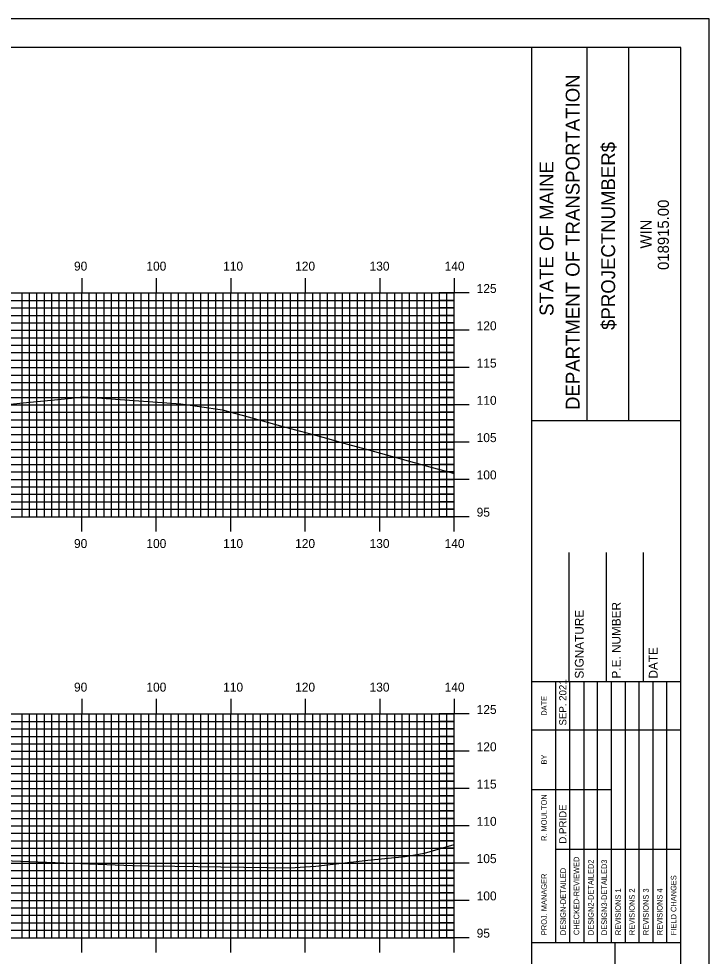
# Model space of a CAD drawing. Extents: x 1754708 to 1755051, y 442591 to 442811.
# Drawn here: x 1754955.1 to 1755047.7, y 442684.8 to 442810.5 of the extents above; entities that cross this region are included whole.
import ezdxf

# ---------------------------------------------------------------- set-up
doc = ezdxf.new("R2010")
doc.units = 0
for name, color, linetype in [('BORDER', 7, 'Continuous'), ('H_V ANNOTATION', 7, 'Continuous'), ('MAJOR', 7, 'Continuous'), ('MINOR', 7, 'Continuous'), ('PLOT BOUNDARY', 7, 'Continuous'), ('S_Roadway_Centerline', 7, 'Continuous')]:
    doc.layers.add(name, color=color, linetype=linetype)

msp = doc.modelspace()

# ---------------------------------------------------------------- linework, layer by layer
at = {"layer": 'BORDER'}
for p, q in [((1755023.92, 442596.67), (1755023.92, 442806.67)), ((1755031.37, 442756.66), (1755031.37, 442806.66)), ((1755036.96, 442756.66), (1755036.96, 442806.66)), ((1755023.92, 442756.65), (1755043.92, 442756.65)), ((1755028.92, 442721.67), (1755028.92, 442738.97)), ((1755033.92, 442721.67), (1755033.92, 442738.97)), ((1755038.92, 442721.67), (1755038.92, 442738.97)), ((1755023.92, 442721.67), (1755043.92, 442721.67)), ((1755023.92, 442686.67), (1755043.92, 442686.67)), ((1755035.1, 442616.67), (1755035.1, 442686.67))]:
    msp.add_line(p, q, dxfattribs=at)
msp.add_lwpolyline([(1754723.92, 442596.67), (1755043.92, 442596.67), (1755043.92, 442806.67), (1754723.92, 442806.67)], close=True, dxfattribs=at)
for points in [[(1755027.15, 442715.17), (1755027.15, 442721.67)], [(1755029.01, 442686.68), (1755029.01, 442721.67)], [(1755030.88, 442721.67), (1755030.88, 442686.68)], [(1755032.74, 442686.68), (1755032.74, 442721.67)], [(1755034.6, 442686.68), (1755034.6, 442721.67)], [(1755036.47, 442686.68), (1755036.47, 442721.67)], [(1755038.33, 442686.68), (1755038.33, 442721.67)], [(1755040.19, 442686.68), (1755040.19, 442721.67)], [(1755042.06, 442686.68), (1755042.06, 442721.67)], [(1755027.15, 442686.68), (1755027.15, 442720.26)], [(1755023.92, 442715.17), (1755043.92, 442715.17)], [(1755023.92, 442707.17), (1755027.15, 442707.17)], [(1755027.15, 442707.17), (1755034.6, 442707.17)], [(1755027.15, 442699.17), (1755043.92, 442699.17)]]:
    msp.add_lwpolyline(points, dxfattribs=at)
at = {"layer": 'MAJOR'}
for p, q in [((1754963.52, 442775.77), (1754963.52, 442773.77)), ((1754973.52, 442775.77), (1754973.52, 442773.77)), ((1754983.52, 442775.77), (1754983.52, 442773.77)), ((1754993.52, 442775.77), (1754993.52, 442773.77)), ((1755003.52, 442775.77), (1755003.52, 442773.77)), ((1755013.52, 442775.77), (1755013.52, 442773.77)), ((1754733.52, 442773.77), (1755013.52, 442773.77)), ((1754733.52, 442773.77), (1755013.52, 442773.77)), ((1754963.52, 442743.77), (1754963.52, 442773.77)), ((1754973.52, 442743.77), (1754973.52, 442773.77)), ((1754983.52, 442743.77), (1754983.52, 442773.77)), ((1754993.52, 442743.77), (1754993.52, 442773.77)), ((1755003.52, 442743.77), (1755003.52, 442773.77)), ((1755015.52, 442773.77), (1755011.51, 442773.77)), ((1755013.52, 442743.77), (1755013.52, 442773.77)), ((1755013.52, 442743.77), (1755013.52, 442773.77)), ((1754733.52, 442768.77), (1755013.52, 442768.77)), ((1755015.52, 442768.77), (1755011.51, 442768.77)), ((1754733.52, 442763.77), (1755013.52, 442763.77)), ((1755015.52, 442763.77), (1755011.51, 442763.77)), ((1754733.52, 442758.77), (1755013.52, 442758.77)), ((1755015.52, 442758.77), (1755011.51, 442758.77)), ((1754733.52, 442753.77), (1755013.52, 442753.77)), ((1755015.52, 442753.77), (1755011.51, 442753.77)), ((1754733.52, 442748.77), (1755013.52, 442748.77)), ((1755015.52, 442748.77), (1755011.51, 442748.77)), ((1754733.52, 442743.77), (1755013.52, 442743.77)), ((1754733.52, 442743.77), (1755013.52, 442743.77)), ((1754963.52, 442741.77), (1754963.52, 442743.77)), ((1754973.52, 442741.77), (1754973.52, 442743.77)), ((1754983.52, 442741.77), (1754983.52, 442743.77)), ((1754993.52, 442741.77), (1754993.52, 442743.77)), ((1755003.52, 442741.77), (1755003.52, 442743.77)), ((1755015.52, 442743.77), (1755011.51, 442743.77)), ((1755013.52, 442741.77), (1755013.52, 442743.77)), ((1754963.52, 442719.32), (1754963.52, 442717.31)), ((1754973.52, 442719.32), (1754973.52, 442717.31)), ((1754983.52, 442719.32), (1754983.52, 442717.31)), ((1754993.52, 442719.32), (1754993.52, 442717.31)), ((1755003.52, 442719.32), (1755003.52, 442717.31)), ((1755013.52, 442719.32), (1755013.52, 442717.31)), ((1754733.52, 442717.31), (1755013.52, 442717.31)), ((1754733.52, 442717.31), (1755013.52, 442717.31)), ((1754963.52, 442687.31), (1754963.52, 442717.31)), ((1754973.52, 442687.31), (1754973.52, 442717.31)), ((1754983.52, 442687.31), (1754983.52, 442717.31)), ((1754993.52, 442687.31), (1754993.52, 442717.31)), ((1755003.52, 442687.31), (1755003.52, 442717.31)), ((1755015.52, 442717.31), (1755011.51, 442717.31)), ((1755013.52, 442687.31), (1755013.52, 442717.31)), ((1755013.52, 442687.31), (1755013.52, 442717.31)), ((1754733.52, 442712.31), (1755013.52, 442712.31)), ((1755015.52, 442712.31), (1755011.51, 442712.31)), ((1754733.52, 442707.31), (1755013.52, 442707.31)), ((1755015.52, 442707.31), (1755011.51, 442707.31)), ((1754733.52, 442702.31), (1755013.52, 442702.31)), ((1755015.52, 442702.31), (1755011.51, 442702.31)), ((1754733.52, 442697.31), (1755013.52, 442697.31)), ((1755015.52, 442697.31), (1755011.51, 442697.31)), ((1754733.52, 442692.31), (1755013.52, 442692.31)), ((1755015.52, 442692.31), (1755011.51, 442692.31)), ((1754733.52, 442687.31), (1755013.52, 442687.31)), ((1754733.52, 442687.31), (1755013.52, 442687.31)), ((1754963.52, 442685.31), (1754963.52, 442687.31)), ((1754973.52, 442685.31), (1754973.52, 442687.31)), ((1754983.52, 442685.31), (1754983.52, 442687.31)), ((1754993.52, 442685.31), (1754993.52, 442687.31)), ((1755003.52, 442685.31), (1755003.52, 442687.31)), ((1755015.52, 442687.31), (1755011.51, 442687.31)), ((1755013.52, 442685.31), (1755013.52, 442687.31))]:
    msp.add_line(p, q, dxfattribs=at)
at = {"layer": 'MINOR'}
for p, q in [((1754733.52, 442772.77), (1755013.52, 442772.77)), ((1754955.52, 442743.77), (1754955.52, 442773.77)), ((1754956.52, 442743.77), (1754956.52, 442773.77)), ((1754957.52, 442743.77), (1754957.52, 442773.77)), ((1754958.52, 442743.77), (1754958.52, 442773.77)), ((1754959.52, 442743.77), (1754959.52, 442773.77)), ((1754960.52, 442743.77), (1754960.52, 442773.77)), ((1754961.52, 442743.77), (1754961.52, 442773.77)), ((1754962.52, 442743.77), (1754962.52, 442773.77)), ((1754964.52, 442743.77), (1754964.52, 442773.77)), ((1754965.52, 442743.77), (1754965.52, 442773.77)), ((1754966.52, 442743.77), (1754966.52, 442773.77)), ((1754967.52, 442743.77), (1754967.52, 442773.77)), ((1754968.52, 442743.77), (1754968.52, 442773.77)), ((1754969.52, 442743.77), (1754969.52, 442773.77)), ((1754970.52, 442743.77), (1754970.52, 442773.77)), ((1754971.52, 442743.77), (1754971.52, 442773.77)), ((1754972.52, 442743.77), (1754972.52, 442773.77)), ((1754974.52, 442743.77), (1754974.52, 442773.77)), ((1754975.52, 442743.77), (1754975.52, 442773.77)), ((1754976.52, 442743.77), (1754976.52, 442773.77)), ((1754977.52, 442743.77), (1754977.52, 442773.77)), ((1754978.52, 442743.77), (1754978.52, 442773.77)), ((1754979.52, 442743.77), (1754979.52, 442773.77)), ((1754980.52, 442743.77), (1754980.52, 442773.77)), ((1754981.52, 442743.77), (1754981.52, 442773.77)), ((1754982.52, 442743.77), (1754982.52, 442773.77)), ((1754984.52, 442743.77), (1754984.52, 442773.77)), ((1754985.52, 442743.77), (1754985.52, 442773.77)), ((1754986.52, 442743.77), (1754986.52, 442773.77)), ((1754987.52, 442743.77), (1754987.52, 442773.77)), ((1754988.52, 442743.77), (1754988.52, 442773.77)), ((1754989.52, 442743.77), (1754989.52, 442773.77)), ((1754990.52, 442743.77), (1754990.52, 442773.77)), ((1754991.52, 442743.77), (1754991.52, 442773.77)), ((1754992.52, 442743.77), (1754992.52, 442773.77)), ((1754994.52, 442743.77), (1754994.52, 442773.77)), ((1754995.52, 442743.77), (1754995.52, 442773.77)), ((1754996.52, 442743.77), (1754996.52, 442773.77)), ((1754997.52, 442743.77), (1754997.52, 442773.77)), ((1754998.52, 442743.77), (1754998.52, 442773.77)), ((1754999.52, 442743.77), (1754999.52, 442773.77)), ((1755000.52, 442743.77), (1755000.52, 442773.77)), ((1755001.52, 442743.77), (1755001.52, 442773.77)), ((1755002.52, 442743.77), (1755002.52, 442773.77)), ((1755004.52, 442743.77), (1755004.52, 442773.77)), ((1755005.52, 442743.77), (1755005.52, 442773.77)), ((1755006.52, 442743.77), (1755006.52, 442773.77)), ((1755007.52, 442743.77), (1755007.52, 442773.77)), ((1755008.52, 442743.77), (1755008.52, 442773.77)), ((1755009.52, 442743.77), (1755009.52, 442773.77)), ((1755010.52, 442743.77), (1755010.52, 442773.77)), ((1755013.52, 442772.77), (1755011.51, 442772.77)), ((1755011.52, 442743.77), (1755011.52, 442773.77)), ((1755012.52, 442743.77), (1755012.52, 442773.77)), ((1754733.52, 442771.77), (1755013.52, 442771.77)), ((1755013.52, 442771.77), (1755011.51, 442771.77)), ((1754733.52, 442770.77), (1755013.52, 442770.77)), ((1755013.52, 442770.77), (1755011.51, 442770.77)), ((1754733.52, 442769.77), (1755013.52, 442769.77)), ((1755013.52, 442769.77), (1755011.51, 442769.77)), ((1754733.52, 442767.77), (1755013.52, 442767.77)), ((1755013.52, 442767.77), (1755011.51, 442767.77)), ((1754733.52, 442766.77), (1755013.52, 442766.77)), ((1755013.52, 442766.77), (1755011.51, 442766.77)), ((1754733.52, 442765.77), (1755013.52, 442765.77)), ((1755013.52, 442765.77), (1755011.51, 442765.77)), ((1754733.52, 442764.77), (1755013.52, 442764.77)), ((1755013.52, 442764.77), (1755011.51, 442764.77)), ((1754733.52, 442762.77), (1755013.52, 442762.77)), ((1755013.52, 442762.77), (1755011.51, 442762.77)), ((1754733.52, 442761.77), (1755013.52, 442761.77)), ((1755013.52, 442761.77), (1755011.51, 442761.77)), ((1754733.52, 442760.77), (1755013.52, 442760.77)), ((1755013.52, 442760.77), (1755011.51, 442760.77)), ((1754733.52, 442759.77), (1755013.52, 442759.77)), ((1755013.52, 442759.77), (1755011.51, 442759.77)), ((1754733.52, 442757.77), (1755013.52, 442757.77)), ((1755013.52, 442757.77), (1755011.51, 442757.77)), ((1754733.52, 442756.77), (1755013.52, 442756.77)), ((1755013.52, 442756.77), (1755011.51, 442756.77)), ((1754733.52, 442755.77), (1755013.52, 442755.77)), ((1755013.52, 442755.77), (1755011.51, 442755.77)), ((1754733.52, 442754.77), (1755013.52, 442754.77)), ((1755013.52, 442754.77), (1755011.51, 442754.77)), ((1754733.52, 442752.77), (1755013.52, 442752.77)), ((1755013.52, 442752.77), (1755011.51, 442752.77)), ((1754733.52, 442751.77), (1755013.52, 442751.77)), ((1755013.52, 442751.77), (1755011.51, 442751.77)), ((1754733.52, 442750.77), (1755013.52, 442750.77)), ((1755013.52, 442750.77), (1755011.51, 442750.77)), ((1754733.52, 442749.77), (1755013.52, 442749.77)), ((1755013.52, 442749.77), (1755011.51, 442749.77)), ((1754733.52, 442747.77), (1755013.52, 442747.77)), ((1755013.52, 442747.77), (1755011.51, 442747.77)), ((1754733.52, 442746.77), (1755013.52, 442746.77)), ((1755013.52, 442746.77), (1755011.51, 442746.77)), ((1754733.52, 442745.77), (1755013.52, 442745.77)), ((1755013.52, 442745.77), (1755011.51, 442745.77)), ((1754733.52, 442744.77), (1755013.52, 442744.77)), ((1755013.52, 442744.77), (1755011.51, 442744.77)), ((1754955.52, 442687.31), (1754955.52, 442717.31)), ((1754956.52, 442687.31), (1754956.52, 442717.31)), ((1754957.52, 442687.31), (1754957.52, 442717.31)), ((1754958.52, 442687.31), (1754958.52, 442717.31)), ((1754959.52, 442687.31), (1754959.52, 442717.31)), ((1754960.52, 442687.31), (1754960.52, 442717.31)), ((1754961.52, 442687.31), (1754961.52, 442717.31)), ((1754962.52, 442687.31), (1754962.52, 442717.31)), ((1754964.52, 442687.31), (1754964.52, 442717.31)), ((1754965.52, 442687.31), (1754965.52, 442717.31)), ((1754966.52, 442687.31), (1754966.52, 442717.31)), ((1754967.52, 442687.31), (1754967.52, 442717.31)), ((1754968.52, 442687.31), (1754968.52, 442717.31)), ((1754969.52, 442687.31), (1754969.52, 442717.31)), ((1754970.52, 442687.31), (1754970.52, 442717.31)), ((1754971.52, 442687.31), (1754971.52, 442717.31)), ((1754972.52, 442687.31), (1754972.52, 442717.31)), ((1754974.52, 442687.31), (1754974.52, 442717.31)), ((1754975.52, 442687.31), (1754975.52, 442717.31)), ((1754976.52, 442687.31), (1754976.52, 442717.31)), ((1754977.52, 442687.31), (1754977.52, 442717.31)), ((1754978.52, 442687.31), (1754978.52, 442717.31)), ((1754979.52, 442687.31), (1754979.52, 442717.31)), ((1754980.52, 442687.31), (1754980.52, 442717.31)), ((1754981.52, 442687.31), (1754981.52, 442717.31)), ((1754982.52, 442687.31), (1754982.52, 442717.31)), ((1754984.52, 442687.31), (1754984.52, 442717.31)), ((1754985.52, 442687.31), (1754985.52, 442717.31)), ((1754986.52, 442687.31), (1754986.52, 442717.31)), ((1754987.52, 442687.31), (1754987.52, 442717.31)), ((1754988.52, 442687.31), (1754988.52, 442717.31)), ((1754989.52, 442687.31), (1754989.52, 442717.31)), ((1754990.52, 442687.31), (1754990.52, 442717.31)), ((1754991.52, 442687.31), (1754991.52, 442717.31)), ((1754992.52, 442687.31), (1754992.52, 442717.31)), ((1754994.52, 442687.31), (1754994.52, 442717.31)), ((1754995.52, 442687.31), (1754995.52, 442717.31)), ((1754996.52, 442687.31), (1754996.52, 442717.31)), ((1754997.52, 442687.31), (1754997.52, 442717.31)), ((1754998.52, 442687.31), (1754998.52, 442717.31)), ((1754999.52, 442687.31), (1754999.52, 442717.31)), ((1755000.52, 442687.31), (1755000.52, 442717.31)), ((1755001.52, 442687.31), (1755001.52, 442717.31)), ((1755002.52, 442687.31), (1755002.52, 442717.31)), ((1755004.52, 442687.31), (1755004.52, 442717.31)), ((1755005.52, 442687.31), (1755005.52, 442717.31)), ((1755006.52, 442687.31), (1755006.52, 442717.31)), ((1755007.52, 442687.31), (1755007.52, 442717.31)), ((1755008.52, 442687.31), (1755008.52, 442717.31)), ((1755009.52, 442687.31), (1755009.52, 442717.31)), ((1755010.52, 442687.31), (1755010.52, 442717.31)), ((1755011.52, 442687.31), (1755011.52, 442717.31)), ((1755012.52, 442687.31), (1755012.52, 442717.31)), ((1754733.52, 442716.31), (1755013.52, 442716.31)), ((1755013.52, 442716.31), (1755011.51, 442716.31)), ((1754733.52, 442715.31), (1755013.52, 442715.31)), ((1755013.52, 442715.31), (1755011.51, 442715.31)), ((1754733.52, 442714.31), (1755013.52, 442714.31)), ((1755013.52, 442714.31), (1755011.51, 442714.31)), ((1754733.52, 442713.31), (1755013.52, 442713.31)), ((1755013.52, 442713.31), (1755011.51, 442713.31)), ((1754733.52, 442711.31), (1755013.52, 442711.31)), ((1755013.52, 442711.31), (1755011.51, 442711.31)), ((1754733.52, 442710.31), (1755013.52, 442710.31)), ((1755013.52, 442710.31), (1755011.51, 442710.31)), ((1754733.52, 442709.31), (1755013.52, 442709.31)), ((1755013.52, 442709.31), (1755011.51, 442709.31)), ((1754733.52, 442708.31), (1755013.52, 442708.31)), ((1755013.52, 442708.31), (1755011.51, 442708.31)), ((1754733.52, 442706.31), (1755013.52, 442706.31)), ((1755013.52, 442706.31), (1755011.51, 442706.31)), ((1754733.52, 442705.31), (1755013.52, 442705.31)), ((1755013.52, 442705.31), (1755011.51, 442705.31)), ((1754733.52, 442704.31), (1755013.52, 442704.31)), ((1755013.52, 442704.31), (1755011.51, 442704.31)), ((1754733.52, 442703.31), (1755013.52, 442703.31)), ((1755013.52, 442703.31), (1755011.51, 442703.31)), ((1754733.52, 442701.31), (1755013.52, 442701.31)), ((1755013.52, 442701.31), (1755011.51, 442701.31)), ((1754733.52, 442700.31), (1755013.52, 442700.31)), ((1755013.52, 442700.31), (1755011.51, 442700.31)), ((1754733.52, 442699.31), (1755013.52, 442699.31)), ((1755013.52, 442699.31), (1755011.51, 442699.31)), ((1754733.52, 442698.31), (1755013.52, 442698.31)), ((1755013.52, 442698.31), (1755011.51, 442698.31)), ((1754733.52, 442696.31), (1755013.52, 442696.31)), ((1755013.52, 442696.31), (1755011.51, 442696.31)), ((1754733.52, 442695.31), (1755013.52, 442695.31)), ((1755013.52, 442695.31), (1755011.51, 442695.31)), ((1754733.52, 442694.31), (1755013.52, 442694.31)), ((1755013.52, 442694.31), (1755011.51, 442694.31)), ((1754733.52, 442693.31), (1755013.52, 442693.31)), ((1755013.52, 442693.31), (1755011.51, 442693.31)), ((1754733.52, 442691.31), (1755013.52, 442691.31)), ((1755013.52, 442691.31), (1755011.51, 442691.31)), ((1754733.52, 442690.31), (1755013.52, 442690.31)), ((1755013.52, 442690.31), (1755011.51, 442690.31)), ((1754733.52, 442689.31), (1755013.52, 442689.31)), ((1755013.52, 442689.31), (1755011.51, 442689.31)), ((1754733.52, 442688.31), (1755013.52, 442688.31)), ((1755013.52, 442688.31), (1755011.51, 442688.31))]:
    msp.add_line(p, q, dxfattribs=at)
at = {"layer": 'PLOT BOUNDARY'}
msp.add_lwpolyline([(1754707.73, 442590.55), (1755047.73, 442590.55), (1755047.73, 442810.55), (1754707.73, 442810.55)], close=True, dxfattribs=at)
at = {"layer": 'S_Roadway_Centerline'}
for points in [[(1754950.94, 442758.55), (1754955.68, 442759.02), (1754960.3, 442759.48), (1754962.17, 442759.66), (1754963.73, 442759.82), (1754968.69, 442759.48), (1754976.83, 442758.92), (1754979.31, 442758.54), (1754982.4, 442758.1), (1754984.03, 442757.65), (1754985.06, 442757.37), (1754990.18, 442755.97), (1754994.9, 442754.68), (1754996.38, 442754.28), (1754999.03, 442753.55), (1755001.18, 442752.96), (1755010.57, 442750.37), (1755012.25, 442749.91), (1755012.74, 442749.77), (1755013.33, 442749.61), (1755013.52, 442749.56)], [(1754953.04, 442697.65), (1754970.33, 442697), (1754972.43, 442696.94), (1754976.01, 442696.89), (1754991.47, 442696.67), (1754994.92, 442696.91), (1755001.93, 442697.7), (1755006.91, 442698.21), (1755009.51, 442698.64), (1755013.52, 442699.81)]]:
    msp.add_lwpolyline(points, dxfattribs=at)

# ---------------------------------------------------------------- texts
at = {"layer": 'BORDER'}
for s, height, p in [('DEPARTMENT OF TRANSPORTATION', 1.8635, (1755030.33, 442758.08)), ('$PROJECTNUMBER$', 1.8635, (1755035.1, 442768.82)), ('STATE OF MAINE', 1.8635, (1755026.83, 442770.69)), ('018915.00', 1.491, (1755042.31, 442776.86)), ('WIN', 1.491, (1755039.99, 442779.73)), ('SIGNATURE', 1.181, (1755030.88, 442722.06)), ('P.E. NUMBER', 1.1811, (1755035.84, 442722.06)), ('DATE', 1.181, (1755040.8, 442722.06)), ('SEP. 2021', 0.969, (1755028.56, 442715.76)), ('DATE', 0.743, (1755025.93, 442717.08)), ('BY', 0.743, (1755025.93, 442710.54)), ('R. MOULTON', 0.745, (1755025.93, 442700.28)), ('D.PRIDE', 0.969, (1755028.56, 442699.92)), ('D.PRIDE', 0.969, (1755028.56, 442699.92)), ('CHECKED-REVIEWED', 0.7455, (1755030.28, 442687.65)), ('DESIGN2-DETAILED2', 0.7455, (1755032.22, 442687.65)), ('DESIGN3-DETAILED3', 0.7455, (1755034.01, 442687.65)), ('DESIGN-DETAILED', 0.7455, (1755028.49, 442687.65)), ('PROJ. MANAGER', 0.7455, (1755025.93, 442687.65)), ('FIELD CHANGES', 0.7455, (1755043.32, 442687.65)), ('REVISIONS 1', 0.7455, (1755035.87, 442687.65)), ('REVISIONS 2', 0.7455, (1755037.73, 442687.65)), ('REVISIONS 3', 0.7455, (1755039.6, 442687.65)), ('REVISIONS 4', 0.7455, (1755041.46, 442687.65))]:
    msp.add_text(s, height=height, rotation=90, dxfattribs=at).set_placement(p)
at = {"layer": 'H_V ANNOTATION'}
for s, p in [('90', (1754962.49, 442776.77)), ('100', (1754972.2, 442776.77)), ('110', (1754982.5, 442776.77)), ('120', (1754992.16, 442776.77)), ('130', (1755002.15, 442776.77)), ('140', (1755012.22, 442776.77)), ('125', (1755016.52, 442773.77)), ('120', (1755016.52, 442768.77)), ('115', (1755016.52, 442763.77)), ('110', (1755016.52, 442758.77)), ('105', (1755016.52, 442753.77)), ('100', (1755016.52, 442748.77)), ('95', (1755016.52, 442743.77)), ('90', (1754962.49, 442739.57)), ('100', (1754972.2, 442739.57)), ('110', (1754982.5, 442739.57)), ('120', (1754992.16, 442739.57)), ('130', (1755002.15, 442739.57)), ('140', (1755012.22, 442739.57)), ('90', (1754962.49, 442720.31)), ('100', (1754972.2, 442720.31)), ('110', (1754982.5, 442720.31)), ('120', (1754992.16, 442720.31)), ('130', (1755002.15, 442720.31)), ('140', (1755012.22, 442720.31)), ('125', (1755016.52, 442717.31)), ('120', (1755016.52, 442712.31)), ('115', (1755016.52, 442707.31)), ('110', (1755016.52, 442702.31)), ('105', (1755016.52, 442697.31)), ('100', (1755016.52, 442692.31)), ('95', (1755016.52, 442687.31))]:
    msp.add_text(s, height=1.2, dxfattribs=at).set_placement(p)

doc.saveas('drawing.dxf')
